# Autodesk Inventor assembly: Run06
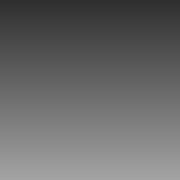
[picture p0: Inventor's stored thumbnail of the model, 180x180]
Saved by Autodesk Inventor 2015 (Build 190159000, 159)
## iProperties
Created: 2013-02
Part Number: Run06
Document SubType Name: Assembly
Designer: Marci
Author: Marci
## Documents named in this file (7)
- C:\Users\Andrew Almeida\Documents\Projeto WS2015\WS2015 CAD Data ANLAS\01\Pneumatic System\Engine\Pneumatikus hajtás\Teljes hajtás\AIP\Tube and Pipe\Run06\Teljes hajtás.Run06.iam
- C:\Users\Andrew Almeida\Documents\Projeto WS2015\WS2015 CAD Data ANLAS\01\Pneumatic System\Engine\Pneumatikus hajtás\Teljes hajtás\AIP\Tube and Pipe\Run06\Teljes hajtás.Hose01.iam
- C:\Users\Andrew Almeida\Documents\Projeto WS2015\WS2015 CAD Data ANLAS\01\Pneumatic System\Engine\Pneumatikus hajtás\Teljes hajtás\AIP\Tube and Pipe\Run06\Teljes hajtás.Hose02.iam
- C:\Users\Andrew Almeida\Documents\Projeto WS2015\WS2015 CAD Data ANLAS\01\Pneumatic System\Engine\Pneumatikus hajtás\Teljes hajtás\AIP\Tube and Pipe\Run06\Teljes hajtás.Hose03.iam
- C:\Users\Andrew Almeida\Documents\Projeto WS2015\WS2015 CAD Data ANLAS\01\Pneumatic System\Engine\Pneumatikus hajtás\Teljes hajtás\AIP\Tube and Pipe\Run06\Teljes hajtás.Hose04.iam
- C:\Users\Andrew Almeida\Documents\Projeto WS2015\WS2015 CAD Data ANLAS\01\Pneumatic System\Engine\Pneumatikus hajtás\Teljes hajtás\AIP\Tube and Pipe\Run06\Teljes hajtás.Hose05.iam
- C:\Users\Andrew Almeida\Documents\Projeto WS2015\WS2015 CAD Data ANLAS\01\Pneumatic System\Engine\Pneumatikus hajtás\Teljes hajtás\AIP\Tube and Pipe\Run06\Teljes hajtás.Hose06.iam
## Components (6 placed, 6 different names)
1. Flexible Hose 01 [sub-assembly]
2. Flexible Hose 02 [sub-assembly]
3. Flexible Hose 03 [sub-assembly]
4. Flexible Hose 04 [sub-assembly]
5. Flexible Hose 05 [sub-assembly]
6. Flexible Hose 06 [sub-assembly]
